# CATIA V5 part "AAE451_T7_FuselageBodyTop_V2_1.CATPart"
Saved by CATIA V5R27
Part number: Part8
Bounding box of the stored display mesh (mm): x -98.453 to 98.453, y -250 to 100, z 0 to 59.98
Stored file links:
  U:\Personal\Downloads\AAE451_T7_FuselageAssemble_V2 (2)\AAE451_T7_FuselageAssemble_V2\AAE451_T7_FuselageBodyTop_V2_1.CATPart
  W:\AAE 451\AAE451_T7_FuselageBody.CATPart
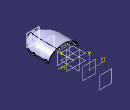
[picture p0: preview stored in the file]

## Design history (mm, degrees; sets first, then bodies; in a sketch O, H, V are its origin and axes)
Body1 (main body)
Body2
  Plane1: type Offset, RefPlane zx-plane, Offset 250, reversed
  Plane2: type Offset, RefPlane zx-plane, Offset 100
  Sketch1 on Plane1, origin (0, -250, 0), H (-1, 0, 0), V (0, 0, 1)
    circle A1 centre (0, 0) radius 35
    distance O A1 = 35
  Plane3: type Offset, RefPlane zx-plane, Offset 150, reversed
  Sketch2 on Plane2, origin (0, 100, 0), H (-1, 0, 0), V (0, 0, 1)
    construction line L1 (0, 60) -> (0, -40)
    point P1 (0, 60)
    construction line L2 (-92.2886, 30) -> (87.7114, 30)
    point P5 (0, 30)
    coincidence: P1 V, P5 L2, P5 L1
    vertical: L1 V
    horizontal: L2 H
  Sketch3 on Plane2, origin (0, 100, 0), H (-1, 0, 0), V (0, 0, 1)
    construction line L1 (0, -100) -> (0, 70)
    point P1 (0, -100)
    construction line L2 (-103.4986, 30) -> (116.5014, 30)
    point P5 (0, 30)
    point P6 (0, 60)
    construction line L3 (-60, 60) -> (60, 60)
    point P7 (-60, 60)
    reference projected curve E1 from Sketch4.E1
    ellipse A1 centre (0, 60) semi-axes 60, 35 rotation 180 from (-60, 60) to (60, 60)
    point P8 (-60, 60)
    point P9 (60, 60)
    point P10 (60, 60)
    point P11 (-60, 60)
    ellipse A2 centre (0, 60) semi-axes 60, 35 rotation 180 from (-60, 60) to (60, 60)
    "Radius" A1 = 60
    "Radius" A1 = 35
    coincidence: P1 V, P5 L2, P5 L1, P6 L1, A1 P7, P7 L3, P6 L3
    vertical: L1 V
    horizontal: L2 H, L3 H, A1 H
    tangency: L3 E1
    symmetry: P9 P10 L3, P8 P11 L3, A1 A2 L3
  Sketch4 on zx-plane, origin (0, 0, 0), H (-1, 0, 0), V (0, 0, 1)
    projected curve E1 from Sketch5.A1
  Sketch5 on Plane3, origin (0, -150, 0), H (-1, 0, 0), V (0, 0, 1)
    construction line L1 (50, 50) -> (50, -50)
    construction line L2 (50, -50) -> (-50, -50)
    construction line L3 (-50, -50) -> (-50, 50)
    construction line L4 (-50, 50) -> (50, 50)
    point P1 (50, 50)
    point P2 (50, -50)
    point P3 (-50, -50)
    point P4 (-50, 50)
    construction line L5 (0, -60) -> (0, 90)
    point P5 (0, -60)
    construction line L6 (-100, 0) -> (110, 0)
    point P7 (-100, 0)
    ellipse A1 centre (0, 0) semi-axes 90.4534, 60 rotation 0
    point P9 (0, 60)
    length L1 = 100
    length L4 = 100
    vertical: L1 V, L3 V, L5 V
    horizontal: L2 H, L4 H, L6 H, A1 H
    equidistance: L1 L3 O, L2 L4 O
    coincidence: P5 V, P7 H, P9 L5, A1 P9, P2 A1, A1 P3, P1 A1, P4 A1
    parallelism: A1 L6
  Loft1: solid, Sections (Sketch3; Sketch4; Sketch5; Sketch1)
  Sketch6 on face of Loft1, origin (0, 100, 0), H (-1, 0, 0), V (0, 0, 1)
    line L1 (-70, 95) -> (70, 95)
    line L2 (70, 95) -> (70, 60)
    line L3 (70, 60) -> (-70, 60)
    line L4 (-70, 60) -> (-70, 95)
    reference projected curve E1 from edge [face of Loft1 | face of Loft1]
    construction line L5 (-60, 60) -> (60, 60)
    length L1 = 140
    horizontal: L1 H, L3 H, L5 H
    vertical: L2 V, L4 V
    coincidence: L3 L5
    tangency: L1 E1
    symmetry: L4 L2 V
  Pocket1: profile Sketch6, direction (0, -1, 0), through (limit type 6)
  Plane4: type Offset, RefPlane Plane2, Offset 100
  Sketch7 on Plane4, origin (0, 200, 0), H (-1, 0, 0), V (0, 0, 1)
    projected line E2 (-60, 60) -> (60, 60) from edge [face of Loft1 | face of Pocket1 from Sketch6.L3]
  Pad1: profile Sketch7, direction (0, 1, 0), up to the existing solid (limit type 3)
  Sketch8 on face of Loft1, origin (0, -250, 0), H (1, 0, 0), V (0, 0, 1)
    line L1 (-100, 0) -> (100, 0)
    point P1 (-100, 0)
    point P2 (100, 0)
    line L2 (-64.2043, -62) -> (64.2043, -62)
    point P3 (-64.2043, -62)
    point P4 (64.2043, -62)
    line L3 (100, 0) -> (64.2043, -62)
    line L4 (-100, 0) -> (-64.2043, -62)
    angle L4 L1 = 60
    distance L1 L2 = 62
    length L1 = 200
    horizontal: L1 H, L2 H
    symmetry: P2 P1 V, P3 P4 V
    coincidence: L1 H
  Pocket2: profile Sketch8, direction (0, 1, 0), through (limit type 6)
  Sketch9 on face of Pocket2 from Sketch8.L1, origin (0, 0, 0), H (1, 0, 0), V (0, -1, 0)
  Sketch10 on start face of Pad1, origin (0, 200, 0), H (-1, 0, 0), V (0, 0, 1)
    circle A1 centre (26, 46.5) radius 6.85
    point P1 (26, 46.5)
    circle A2 centre (-26, 46.5) radius 6.85
    reference projected line E1 (60, 60) -> (-60, 60) from edge [face of Pad1 | start face of Pad1]
    radius A1 = 6.85
    distance V P1 = 26
    distance E1 P1 = 13.5
    symmetry: A2 A1 V
  Pocket3: profile Sketch10, direction (0, -1, 0), length 300
  Plane5 "MOTOR": type Offset, RefPlane Plane1, Offset 4
  Plane6 "BATTERY": type Offset, RefPlane Plane1, Offset 88.5
  Shell1: ExtOffset 0, Face face of Pocket2 from Sketch8.L1, IntOffset 2
  Plane7: type Offset, RefPlane xy-plane, Offset 40
  Sketch11 on Plane7, origin (0, 0, 40), H (1, 0, 0), V (0, 1, 0)
    line L1 (69.2382, 78.9472) -> (-67.3756, 82.6205)
  Pad2: profile Sketch11, direction (0, 0, 1), up to the existing solid (limit type 2)
  Sketch12 on face of Pocket2 from Sketch8.L1, origin (0, 0, 0), H (1, 0, 0), V (0, -1, 0)
    arc A1 centre (-93.4533, 150) radius 5 from (-93.4533, 155) to (-93.4533, 145) ccw
    point P1 (-93.4533, 150)
    line L1 (-93.4533, 145) -> (-88.4533, 145)
    line L2 (-88.4533, 145) -> (-88.4533, 155)
    line L3 (-88.4533, 155) -> (-93.4533, 155)
    reference projected curve E1 from edge [face of Shell1 | face of Pocket2 from Sketch8.L1]
    reference intersected line E2 through (0, 150) direction (1, 0) from Plane3
    distance P1 L2 = 5
    distance L3 L1 = 10
    horizontal: L1 H, L3 H
    tangency: L2 E1, L1 A1, L3 A1
    coincidence: E2 P1
    vertical: L2 V
  Pad3: profile Sketch12, direction (0, 0, 1), length 10
  Sketch13 on face of Pad3, origin (0, 0, 0), H (1, 0, 0), V (0, -1, 0)
    circle A1 centre (-93.4534, 150) radius 2.5
    reference projected arc E1 centre (-93.4534, 150) radius 5 from (-93.4534, 155) to (-93.4534, 145) ccw from edge [face of Pad3 from Sketch12.A1 | start face of Pad3]
    radius A1 = 2.5
    concentricity: A1 E1
  Pocket4: profile Sketch13, direction (0, 0, 1), through (limit type 6)
  RectPattern1: of Pad3, direction 1 instances 3, spacing 75, along yz-plane
  RectPattern2: of Pocket4, direction 1 instances 3, spacing 75, along yz-plane
  Mirror1: of RectPattern1, about yz-plane
  Mirror2: of RectPattern2, about yz-plane
  Plane8 "PRINT CAPACITY": type Offset, RefPlane Plane4, Offset 260, reversed
  Sketch14 on start face of Pad1, origin (0, 200, 0), H (-1, 0, 0), V (0, 0, 1)
    projected circle E1 centre (26, 46.5) radius 6.85 from edge [start face of Pad1 | face of Pocket3 from Sketch10.A1]
    projected circle E2 centre (-26, 46.5) radius 6.85 from edge [start face of Pad1 | face of Pocket3 from Sketch10.A2]
  Pocket5: profile Sketch14, direction (0, -1, 0), length 300
  Sketch15 on Plane8, origin (0, -60, 0), H (-1, 0, 0), V (0, 0, 1)
    point P1 (0, 30)
    line L1 (132.2054, 60) -> (132.2054, 0)
    line L2 (132.2054, 0) -> (-132.2054, 0)
    line L3 (-132.2054, 0) -> (-132.2054, 60)
    line L4 (-132.2054, 60) -> (132.2054, 60)
    reference projected line E1 (60, 60) -> (-60, 60) from edge [face of Pad1 from Sketch7.E2 | start face of Pad1]
    vertical: L1 V, L3 V
    horizontal: L2 H, L4 H
    equidistance: L1 L3 P1, L2 L4 P1
    coincidence: L4 E1, L2 H
    symmetry: L3 L1 V
  Pocket6: profile Sketch15, direction (0, 1, 0), through (limit type 6)
  Sketch16 on Plane5, origin (0, -246, 0), H (-1, 0, 0), V (0, 0, 1)
    arc A1 centre (0, 0) radius 30 from (30, 0) to (-30, 0) ccw
    line L1 (-30, 0) -> (30, 0)
    point P1 (30, 0)
    point P3 (30, 0)
    radius A1 = 30
    coincidence: L1 H, P1 P3
  Pad4: profile Sketch16, direction (0, 1, 0), up to the existing solid (limit type 3)
  Sketch17 on face of Loft1, origin (7.8105, -250, 15.3841), H (1, 0, 0), V (0, 0, 1)
    point P1 (11.9395, 4.3659)
    reference intersected line E1 through (-7.8105, 0) direction (0, 1) from yz-plane
    reference projected line E2 (27.1895, -15.3841) -> (-42.8105, -15.3841) from edge [face of Loft1 | face of RectPattern1]
    distance E1 P1 = 19.75
    distance E2 P1 = 19.75
  Hole1: placed by Sketch17, at (19.75, -250, 19.75) direction (0, 1, 0), diameter 3.5, through (limit type 6)
  Mirror3: of Hole1, about yz-plane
